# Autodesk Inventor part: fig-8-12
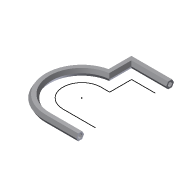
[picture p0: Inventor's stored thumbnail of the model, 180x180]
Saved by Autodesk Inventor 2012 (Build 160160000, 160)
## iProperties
Created: 2004-05
Part Number: fig-8-12
Document SubType Name: Modeling
Designer: CADCIM Technologies
Manufacturer: Standard
Standards Organization: Custom
Density: 1 g/cm^3
Material: Default
Author: CADCIM Technologies
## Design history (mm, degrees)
sketch "Sketch1"
  geometry: L1 (-42.583, 3.219)-(-90.066, 3.219); L2 (-90.066, 58.92)-(-77.282, 58.92); L3 (-77.282, 58.92)-(-77.282, 91.063); L4 (-77.282, 91.063)-(-42.583, 91.063); A1 r 27.851 centre (-90.066, 31.07) between (-90.066, 58.92) and (-90.066, 3.219)
  constraints: 8 end point, 2 parallel, 2 point on circle, 2 tangent, 1 centre point, 1 perpendicular
workplane "Work Plane2"
sweep "Sweep5" dims "d4" = 0
body "Solid1"
sketch "Sketch2"
  geometry: L1 (16.303, 0)-(19.151, 4.934); L2 (19.151, 4.934)-(24.849, 4.934); L3 (24.849, 4.934)-(27.697, 0); L4 (27.697, 0)-(24.849, -4.934); L5 (24.849, -4.934)-(19.151, -4.934); L6 (19.151, -4.934)-(16.303, 0); L7 (18.744, 0)-(20.372, 2.819); L8 (20.372, 2.819)-(23.628, 2.819); L9 (23.628, 2.819)-(25.256, 0); L10 (25.256, 0)-(23.628, -2.819); L11 (23.628, -2.819)-(20.372, -2.819); L12 (20.372, -2.819)-(18.744, 0); 2 further points
  constraints: 24 end point, 1 coincident, 22 other
